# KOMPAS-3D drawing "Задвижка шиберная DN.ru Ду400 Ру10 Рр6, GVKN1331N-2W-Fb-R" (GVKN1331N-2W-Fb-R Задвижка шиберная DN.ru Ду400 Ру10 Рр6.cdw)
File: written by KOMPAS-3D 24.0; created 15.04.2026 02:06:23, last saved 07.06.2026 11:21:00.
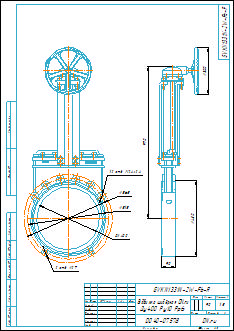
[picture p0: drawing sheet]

Document properties: Автор: DN.ru; Форматы листов документа: A3; Полное имя файла: GVKN1331N-2W-Fb-R Задвижка шиберная DN.ru Ду400 Ру10 Рр6.m3d; Масса: 90; Наименование: Задвижка шиберная DN.ru Ду400 Ру10 Рр6; Количество листов документа: 1; Примечание: D040-07578

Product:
- Part/product: Задвижка шиберная DN.ru Ду400 Ру10 Рр6  | designation GVKN1331N-2W-Fb-R
    Масса: 90
    Раздел спецификации: Прочие изделия
    Примечание: D040-07578

Views: Вид 1, Вид:1
Referenced files in C:\Работа\GVKN1331N-2W-Fb-R Задвижка шиберная DN.ru Ду400-600 Ру10\DN400\: GVKN1331N-2W-Fb-R Задвижка шиберная DN.ru Ду400 Ру10.m3d
Referenced files in E:\Работа\Зайцев\АУТСОРС\Даня\GVKN1331N-2W-Fb-R Задвижка шиберная DN.ru Ду400-600 Ру4-6\исходные материалы\DN400\DN400\: GVKN1331N-2W-Fb-R Задвижка шиберная DN.ru Ду400 Ру10 Рр6.m3d
Referenced files in C:\Program Files\ASCON\KOMPAS-3D v24\Templates\: Чертеж_DN.ru.cdt
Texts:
  GVKN1331N-2W-Fb-R
  Чертеж_DN.ru.cdt
  Задвижка шиберная DN.ru
  Ду400 Ру10 Рр6
  Задвижка шиберная DN.ru Ду400 Ру10 Рр6
  GVKN1331N-2W-Fb-R Задвижка шиберная DN.ru Ду400 Ру10 Рр6
Dimensions and other numbers on the sheet: 0; 3; 2; 4; 400; 565; 515; 12 отв.; 24; 2 отв.; 27; 1; 1:5; 90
